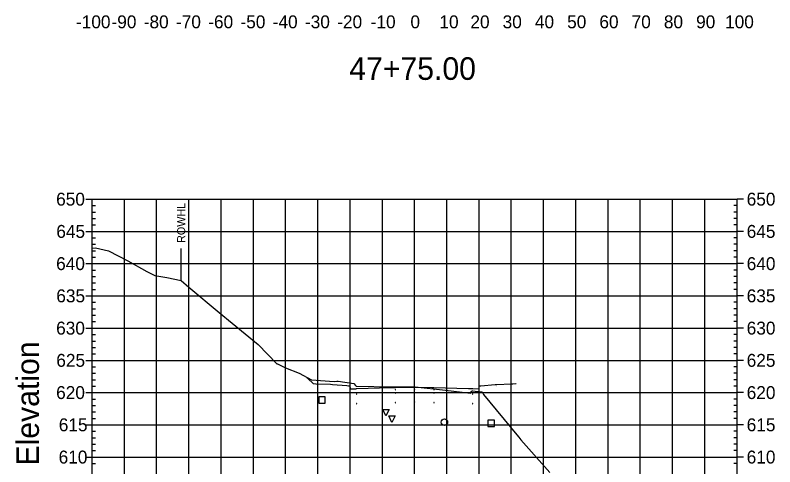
# Model space of a CAD drawing. Extents: x 708103 to 717568, y 374476 to 378707.
# Drawn here: x 712228.1 to 712463.7, y 378241.6 to 378381.7 of the extents above; entities that cross this region are included whole.
import ezdxf

# ---------------------------------------------------------------- set-up
doc = ezdxf.new("R2010")
doc.units = 0
for name, color, linetype in [('1', 7, 'Continuous'), ('10', 7, 'Continuous'), ('13', 7, 'Continuous'), ('14', 7, 'Continuous'), ('22', 7, 'Continuous'), ('4', 7, 'Continuous'), ('57', 7, 'Continuous'), ('60', 7, 'Continuous'), ('Existing', 7, 'Continuous'), ('XS_Right_of_Way', 7, 'Continuous')]:
    doc.layers.add(name, color=color, linetype=linetype)

msp = doc.modelspace()

# ---------------------------------------------------------------- linework, layer by layer
for points in [[(712345.93, 378265.49), (712346.03, 378265.49), (712346.03, 378265.59), (712345.93, 378265.59)], [(712351.93, 378265.61), (712352.03, 378265.61), (712352.03, 378265.71), (712351.93, 378265.71)], [(712357.93, 378265.49), (712358.03, 378265.49), (712358.03, 378265.59), (712357.93, 378265.59)], [(712333.93, 378264.13), (712334.03, 378264.13), (712334.03, 378264.23), (712333.93, 378264.23)], [(712345.93, 378264.49), (712346.03, 378264.49), (712346.03, 378264.59), (712345.93, 378264.59)], [(712351.93, 378264.61), (712352.03, 378264.61), (712352.03, 378264.71), (712351.93, 378264.71)], [(712357.93, 378264.49), (712358.03, 378264.49), (712358.03, 378264.59), (712357.93, 378264.59)], [(712369.93, 378264.13), (712370.03, 378264.13), (712370.03, 378264.23), (712369.93, 378264.23)], [(712333.93, 378261.13), (712334.03, 378261.13), (712334.03, 378261.23), (712333.93, 378261.23)], [(712345.93, 378261.49), (712346.03, 378261.49), (712346.03, 378261.59), (712345.93, 378261.59)], [(712351.93, 378261.61), (712352.03, 378261.61), (712352.03, 378261.71), (712351.93, 378261.71)], [(712357.93, 378261.49), (712358.03, 378261.49), (712358.03, 378261.59), (712357.93, 378261.59)], [(712369.93, 378261.13), (712370.03, 378261.13), (712370.03, 378261.23), (712369.93, 378261.23)]]:
    msp.add_lwpolyline(points, close=True)
at = {"layer": '1'}
for points in [[(712343.1, 378257.42), (712342.1, 378259.42), (712344.1, 378259.42)], [(712344.96, 378255.4), (712343.96, 378257.4), (712345.96, 378257.4)]]:
    msp.add_lwpolyline(points, close=True, dxfattribs=at)
at = {"layer": '10'}
msp.add_lwpolyline([(712322.29, 378261.34), (712324.29, 378261.34), (712324.29, 378263.34), (712322.29, 378263.34)], close=True, dxfattribs=at)
at = {"layer": '13'}
msp.add_circle((712361.22, 378255.46), 1, dxfattribs=at)
at = {"layer": '14'}
for points in [[(712318.56, 378269.33), (712318.56, 378269.38), (712318.56, 378269.33), (712318.51, 378269.33), (712318.56, 378269.33), (712318.56, 378269.28), (712318.56, 378269.33), (712318.61, 378269.33)], [(712333.98, 378265.85), (712333.98, 378265.9), (712333.98, 378265.85), (712333.93, 378265.85), (712333.98, 378265.85), (712333.98, 378265.8), (712333.98, 378265.85), (712334.03, 378265.85)], [(712351.98, 378266.33), (712351.98, 378266.38), (712351.98, 378266.33), (712351.93, 378266.33), (712351.98, 378266.33), (712351.98, 378266.28), (712351.98, 378266.33), (712352.03, 378266.33)], [(712369.98, 378265.85), (712369.98, 378265.9), (712369.98, 378265.85), (712369.93, 378265.85), (712369.98, 378265.85), (712369.98, 378265.8), (712369.98, 378265.85), (712370.03, 378265.85)]]:
    msp.add_lwpolyline(points, dxfattribs=at)
at = {"layer": '22'}
msp.add_lwpolyline([(712318.56, 378269.33), (712318.86, 378269.03), (712320.48, 378267.41), (712321.38, 378267.37), (712321.48, 378267.37), (712325.94, 378267.19), (712326.48, 378267.17), (712330.94, 378266.81), (712331.48, 378266.77), (712331.86, 378266.77), (712331.9, 378266.77), (712331.98, 378265.87), (712331.98, 378265.77), (712333.77, 378265.84), (712333.98, 378265.85), (712344.69, 378266.17), (712345.98, 378266.21), (712351.34, 378266.31), (712351.98, 378266.33), (712357.34, 378266.22), (712357.98, 378266.21), (712368.7, 378265.88), (712369.98, 378265.85), (712371.77, 378265.77), (712371.98, 378265.77), (712372.06, 378266.66), (712372.07, 378266.77), (712372.44, 378266.77), (712372.48, 378266.77), (712376.95, 378267.12), (712377.48, 378267.17), (712381.95, 378267.34), (712382.48, 378267.37), (712383.38, 378267.4), (712383.48, 378267.41)], dxfattribs=at)
at = {"layer": '4'}
msp.add_lwpolyline([(712374.72, 378254.12), (712376.72, 378254.12), (712376.72, 378256.12), (712374.72, 378256.12)], close=True, dxfattribs=at)
at = {"layer": '57'}
for p, q in [((712249.98, 378324.63), (712251.98, 378324.63)), ((712251.98, 378324.63), (712451.98, 378324.63)), ((712251.98, 378194.63), (712251.98, 378324.63)), ((712251.98, 378194.63), (712251.98, 378324.63)), ((712261.98, 378194.63), (712261.98, 378324.63)), ((712271.98, 378194.63), (712271.98, 378324.63)), ((712281.98, 378194.63), (712281.98, 378324.63)), ((712291.98, 378194.63), (712291.98, 378324.63)), ((712301.98, 378194.63), (712301.98, 378324.63)), ((712311.98, 378194.63), (712311.98, 378324.63)), ((712321.98, 378194.63), (712321.98, 378324.63)), ((712331.98, 378194.63), (712331.98, 378324.63)), ((712341.98, 378194.63), (712341.98, 378324.63)), ((712351.98, 378194.63), (712351.98, 378324.63)), ((712361.98, 378194.63), (712361.98, 378324.63)), ((712371.98, 378194.63), (712371.98, 378324.63)), ((712381.98, 378194.63), (712381.98, 378324.63)), ((712391.98, 378194.63), (712391.98, 378324.63)), ((712401.98, 378194.63), (712401.98, 378324.63)), ((712411.98, 378194.63), (712411.98, 378324.63)), ((712421.98, 378194.63), (712421.98, 378324.63)), ((712431.98, 378194.63), (712431.98, 378324.63)), ((712441.98, 378194.63), (712441.98, 378324.63)), ((712451.98, 378194.63), (712451.98, 378324.63)), ((712451.98, 378194.63), (712451.98, 378324.63)), ((712453.98, 378324.63), (712451.98, 378324.63)), ((712251.98, 378322.63), (712252.98, 378322.63)), ((712451.98, 378322.63), (712450.98, 378322.63)), ((712251.98, 378320.63), (712252.98, 378320.63)), ((712451.98, 378320.63), (712450.98, 378320.63)), ((712251.98, 378318.63), (712252.98, 378318.63)), ((712451.98, 378318.63), (712450.98, 378318.63)), ((712249.98, 378314.63), (712251.98, 378314.63)), ((712251.98, 378316.63), (712252.98, 378316.63)), ((712251.98, 378314.63), (712451.98, 378314.63)), ((712451.98, 378316.63), (712450.98, 378316.63)), ((712453.98, 378314.63), (712451.98, 378314.63)), ((712251.98, 378312.63), (712252.98, 378312.63)), ((712451.98, 378312.63), (712450.98, 378312.63)), ((712251.98, 378310.63), (712252.98, 378310.63)), ((712451.98, 378310.63), (712450.98, 378310.63)), ((712251.98, 378308.63), (712252.98, 378308.63)), ((712451.98, 378308.63), (712450.98, 378308.63)), ((712251.98, 378306.63), (712252.98, 378306.63)), ((712451.98, 378306.63), (712450.98, 378306.63)), ((712249.98, 378304.63), (712251.98, 378304.63)), ((712251.98, 378304.63), (712451.98, 378304.63)), ((712453.98, 378304.63), (712451.98, 378304.63)), ((712251.98, 378302.63), (712252.98, 378302.63)), ((712251.98, 378300.63), (712252.98, 378300.63)), ((712451.98, 378302.63), (712450.98, 378302.63)), ((712451.98, 378300.63), (712450.98, 378300.63)), ((712251.98, 378298.63), (712252.98, 378298.63)), ((712451.98, 378298.63), (712450.98, 378298.63)), ((712251.98, 378296.63), (712252.98, 378296.63)), ((712451.98, 378296.63), (712450.98, 378296.63)), ((712249.98, 378294.63), (712251.98, 378294.63)), ((712251.98, 378294.63), (712451.98, 378294.63)), ((712453.98, 378294.63), (712451.98, 378294.63)), ((712251.98, 378292.63), (712252.98, 378292.63)), ((712451.98, 378292.63), (712450.98, 378292.63)), ((712251.98, 378290.63), (712252.98, 378290.63)), ((712251.98, 378288.63), (712252.98, 378288.63)), ((712451.98, 378290.63), (712450.98, 378290.63)), ((712451.98, 378288.63), (712450.98, 378288.63)), ((712251.98, 378286.63), (712252.98, 378286.63)), ((712451.98, 378286.63), (712450.98, 378286.63)), ((712249.98, 378284.63), (712251.98, 378284.63)), ((712251.98, 378284.63), (712451.98, 378284.63)), ((712453.98, 378284.63), (712451.98, 378284.63)), ((712251.98, 378282.63), (712252.98, 378282.63)), ((712451.98, 378282.63), (712450.98, 378282.63)), ((712251.98, 378280.63), (712252.98, 378280.63)), ((712451.98, 378280.63), (712450.98, 378280.63)), ((712251.98, 378278.63), (712252.98, 378278.63)), ((712451.98, 378278.63), (712450.98, 378278.63)), ((712249.98, 378274.63), (712251.98, 378274.63)), ((712251.98, 378276.63), (712252.98, 378276.63)), ((712251.98, 378274.63), (712451.98, 378274.63)), ((712451.98, 378276.63), (712450.98, 378276.63)), ((712453.98, 378274.63), (712451.98, 378274.63)), ((712251.98, 378272.63), (712252.98, 378272.63)), ((712451.98, 378272.63), (712450.98, 378272.63)), ((712251.98, 378270.63), (712252.98, 378270.63)), ((712451.98, 378270.63), (712450.98, 378270.63)), ((712251.98, 378268.63), (712252.98, 378268.63)), ((712451.98, 378268.63), (712450.98, 378268.63)), ((712251.98, 378266.63), (712252.98, 378266.63)), ((712451.98, 378266.63), (712450.98, 378266.63)), ((712249.98, 378264.63), (712251.98, 378264.63)), ((712251.98, 378264.63), (712451.98, 378264.63)), ((712453.98, 378264.63), (712451.98, 378264.63)), ((712251.98, 378262.63), (712252.98, 378262.63)), ((712251.98, 378260.63), (712252.98, 378260.63)), ((712451.98, 378262.63), (712450.98, 378262.63)), ((712451.98, 378260.63), (712450.98, 378260.63)), ((712251.98, 378258.63), (712252.98, 378258.63)), ((712451.98, 378258.63), (712450.98, 378258.63)), ((712251.98, 378256.63), (712252.98, 378256.63)), ((712451.98, 378256.63), (712450.98, 378256.63)), ((712249.98, 378254.63), (712251.98, 378254.63)), ((712251.98, 378254.63), (712451.98, 378254.63)), ((712453.98, 378254.63), (712451.98, 378254.63)), ((712251.98, 378252.63), (712252.98, 378252.63)), ((712451.98, 378252.63), (712450.98, 378252.63)), ((712251.98, 378250.63), (712252.98, 378250.63)), ((712251.98, 378248.63), (712252.98, 378248.63)), ((712451.98, 378250.63), (712450.98, 378250.63)), ((712451.98, 378248.63), (712450.98, 378248.63)), ((712251.98, 378246.63), (712252.98, 378246.63)), ((712451.98, 378246.63), (712450.98, 378246.63)), ((712249.98, 378244.63), (712251.98, 378244.63)), ((712251.98, 378244.63), (712451.98, 378244.63)), ((712453.98, 378244.63), (712451.98, 378244.63)), ((712251.98, 378242.63), (712252.98, 378242.63)), ((712451.98, 378242.63), (712450.98, 378242.63))]:
    msp.add_line(p, q, dxfattribs=at)
at = {"layer": 'Existing'}
msp.add_lwpolyline([(712251.98, 378309.4), (712253.07, 378309.53), (712257.03, 378308.62), (712263.08, 378305.51), (712268.96, 378302.23), (712271.47, 378300.92), (712275.1, 378300.34), (712279.56, 378299.42), (712282.01, 378297.38), (712291.39, 378289.48), (712303.5, 378279.51), (712309.24, 378273.56), (712309.43, 378273.58), (712311.92, 378272.27), (712316.14, 378270.64), (712320.02, 378268.54), (712326.99, 378268.1), (712327.89, 378268.21), (712328.28, 378268.19), (712333.09, 378267.49), (712333.69, 378266.78), (712333.84, 378266.57), (712344.93, 378266.4), (712352.16, 378266.37), (712361.59, 378265.42), (712369.28, 378264.5), (712369.63, 378264.92), (712369.76, 378265.18), (712370.04, 378265.14), (712370.75, 378265.09), (712372.92, 378264.85), (712373.32, 378264), (712383.71, 378251.57), (712384.27, 378250.8), (712384.94, 378250.01), (712393.95, 378239.89)], dxfattribs=at)
at = {"layer": 'XS_Right_of_Way'}
msp.add_line((712279.52, 378309.29), (712279.52, 378299.29), dxfattribs=at)

# ---------------------------------------------------------------- texts
at = {"layer": '1'}
msp.add_text('47+75.00', height=7, dxfattribs=at).set_placement((712331.71, 378361.63))
at = {"layer": '14'}
for p in [(712321.45, 378267.32), (712382.45, 378267.32), (712321.45, 378266.65), (712326.45, 378266.45), (712377.45, 378266.45), (712382.45, 378266.65)]:
    msp.add_text('+', height=0.1, dxfattribs=at).set_placement(p)
at = {"layer": '57'}
for s, p in [('-100', (712246.97, 378377.63)), ('-90', (712257.98, 378377.63)), ('-80', (712267.98, 378377.63)), ('-70', (712277.98, 378377.63)), ('-60', (712287.98, 378377.63)), ('-50', (712297.98, 378377.63)), ('-40', (712307.98, 378377.63)), ('-30', (712317.98, 378377.63)), ('-20', (712327.98, 378377.63)), ('-10', (712338.37, 378377.63)), ('0', (712350.69, 378377.63)), ('10', (712359.68, 378377.63)), ('20', (712369.29, 378377.63)), ('30', (712379.29, 378377.63)), ('40', (712389.29, 378377.63)), ('50', (712399.29, 378377.63)), ('60', (712409.29, 378377.63)), ('70', (712419.29, 378377.63)), ('80', (712429.29, 378377.63)), ('90', (712439.29, 378377.63)), ('100', (712448.28, 378377.63)), ('650', (712240.81, 378322.63)), ('650', (712454.98, 378322.63)), ('645', (712240.86, 378312.63)), ('645', (712454.98, 378312.63)), ('640', (712240.81, 378302.63)), ('640', (712454.98, 378302.63)), ('635', (712240.86, 378292.63)), ('635', (712454.98, 378292.63)), ('630', (712240.81, 378282.63)), ('630', (712454.98, 378282.63)), ('625', (712240.86, 378272.63)), ('625', (712454.98, 378272.63)), ('620', (712240.81, 378262.63)), ('620', (712454.98, 378262.63)), ('615', (712241.63, 378252.63)), ('615', (712454.98, 378252.63)), ('610', (712241.58, 378242.63)), ('610', (712454.98, 378242.63))]:
    msp.add_text(s, height=4, dxfattribs=at).set_placement(p)
at = {"layer": '60'}
msp.add_text('Elevation', height=7, rotation=90, dxfattribs=at).set_placement((712235.48, 378241.99))
at = {"layer": 'XS_Right_of_Way'}
msp.add_text('ROWHL', height=2.5, rotation=90, dxfattribs=at).set_placement((712280.84, 378311.05))

doc.saveas('drawing.dxf')
